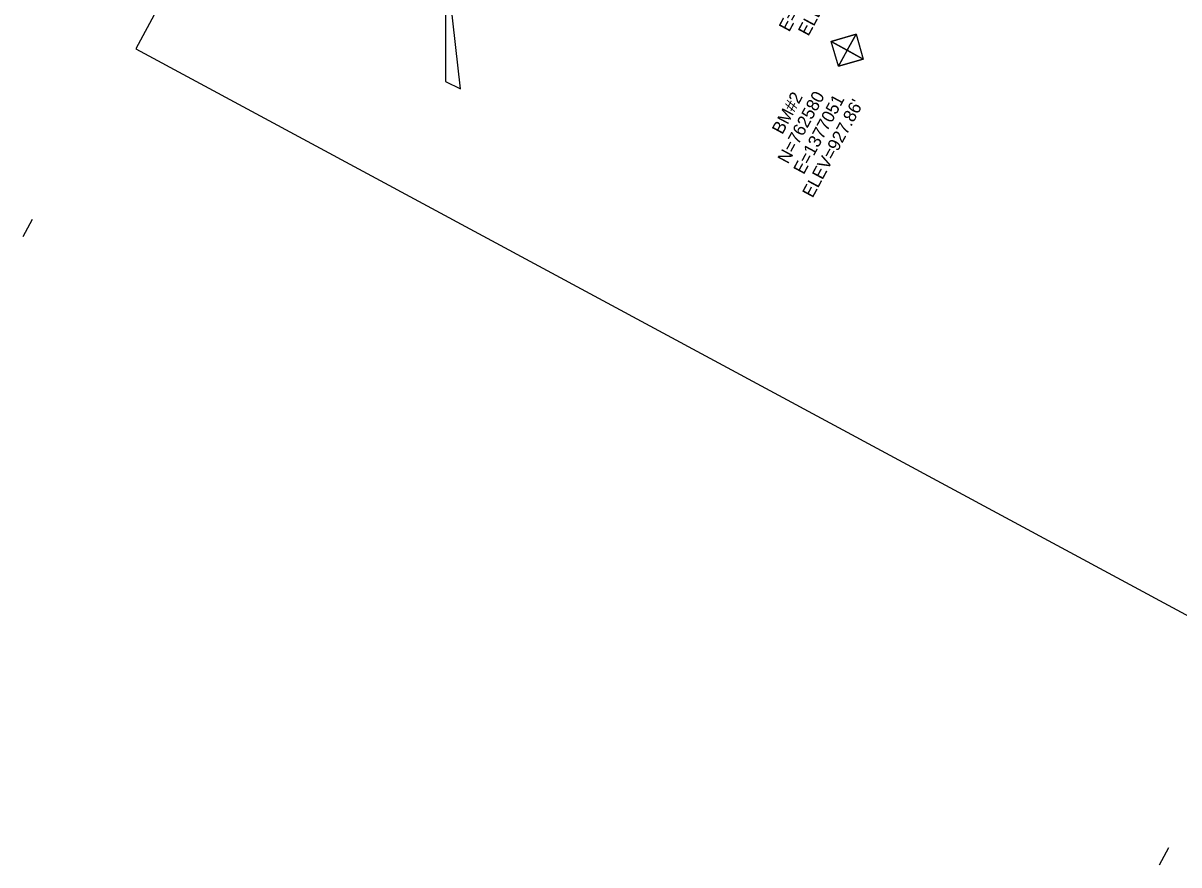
# Model space of a CAD drawing. Extents: x 1376594 to 1378079, y 762010 to 763753.
# Drawn here: x 1376594 to 1377235, y 762128 to 762595 of the extents above; entities that cross this region are included whole.
import ezdxf

# ---------------------------------------------------------------- set-up
doc = ezdxf.new("R2010")
doc.units = 0
for name, color, linetype in [('CTL Bench Mark CELL', 7, 'Continuous'), ('CTL GPS Vertical Text', 7, 'Continuous'), ('CTL North Arrow NAD 83 NSRS 2007 CELL', 7, 'Continuous'), ('CTL Sheet Border CELL', 7, 'Continuous'), ('Default', 7, 'Continuous')]:
    doc.layers.add(name, color=color, linetype=linetype)

# ---------------------------------------------------------------- blocks, each defined once
blk = doc.blocks.new('CTL NORTH ARROW NAD 83 NSRS 2007')
at = {"layer": 'Default'}
blk.add_line((0, 0), (0, 0), dxfattribs=at)
for points in [[(-0.003, 1.746), (-0.003, 0.579), (0.135, 0.511)], [(-0.168, -0.065), (-0.154, -0.065), (-0.154, 0.401), (0.135, -0.065), (0.148, -0.065), (0.148, 0.428), (0.135, 0.428), (0.135, -0.038), (-0.154, 0.428), (-0.168, 0.428)], [(-0.003, -1.671), (0.135, -1.739), (-0.003, -0.505)]]:
    blk.add_lwpolyline(points, close=True, dxfattribs=at)
blk.add_lwpolyline([(-0.003, 0.579), (-0.003, -0.107)], dxfattribs=at)
for s, p in [('NC GRID', (-0.345, -0.267)), ('NAD 83/NSRS 2007', (-0.888, -0.46))]:
    blk.add_text(s, height=0.12, dxfattribs=at).set_placement(p)
blk = doc.blocks.new('CTL BENCH MARK')
at = {"layer": 'CTL Bench Mark CELL'}
blk.add_line((0, 0), (0, 0), dxfattribs=at)
blk.add_lwpolyline([(-0.072, 0.07175), (0.07175, 0.07175), (0.07175, -0.072), (-0.072, -0.072)], close=True, dxfattribs=at)
for points in [[(0.07175, 0.07175), (-0.072, -0.072), (-0.000125, -0.000125), (0.07175, -0.072), (-0.072, 0.07175)], [(-0.000125, -0.000125), (0.07175, 0.07175), (-0.072, 0.07175), (-0.000125, -0.000125)], [(-0.000125, -0.000125), (-0.072, -0.072), (0.07175, -0.072), (-0.000125, -0.000125)]]:
    blk.add_lwpolyline(points, dxfattribs=at)

msp = doc.modelspace()

# ---------------------------------------------------------------- linework, layer by layer
at = {"layer": 'CTL Sheet Border CELL'}
for p, q in [((1376593.78, 762476.93), (1376598.93, 762486.5)), ((1377224.53, 762128.06), (1377229.69, 762137.62))]:
    msp.add_line(p, q, dxfattribs=at)
msp.add_lwpolyline([(1377275.23, 763729.25), (1376656.26, 762581.12), (1377459.94, 762147.84), (1378078.92, 763295.97)], close=True, dxfattribs=at)

# ---------------------------------------------------------------- block references
at = {"layer": 'CTL Bench Mark CELL', "xscale": 99.99999999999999, "yscale": 100, "rotation": -163.84591254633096}
msp.add_blockref('CTL BENCH MARK', (1377051.19, 762580.28), dxfattribs=at)
at = {"layer": 'CTL North Arrow NAD 83 NSRS 2007 CELL', "xscale": 60, "yscale": 60}
msp.add_blockref('CTL NORTH ARROW NAD 83 NSRS 2007', (1376828.36, 762663.15), dxfattribs=at)

# ---------------------------------------------------------------- texts
at = {"layer": 'CTL GPS Vertical Text'}
for s, p in [('E=1377046.991', (1377018.97, 762590.09)), ("ELEV=933.40'", (1377029.62, 762587.73)), ('BM#2', (1377015.16, 762533.13)), ('N=762580', (1377018.28, 762516.8)), ('E=1377051', (1377027.04, 762510.92)), ("ELEV=927.86'", (1377031.97, 762497.93))]:
    msp.add_text(s, height=7, rotation=61.67024, dxfattribs=at).set_placement(p)

doc.saveas('drawing.dxf')
